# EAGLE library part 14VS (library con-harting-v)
CONNECTOR
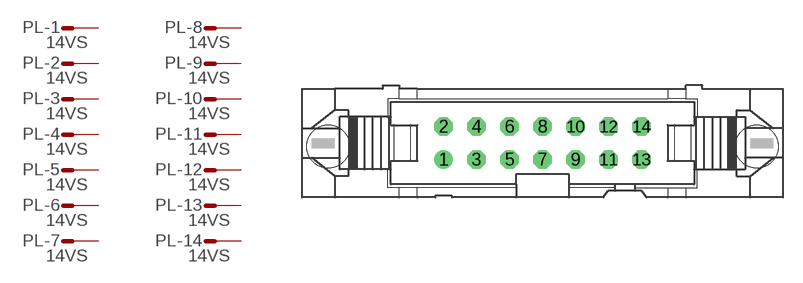
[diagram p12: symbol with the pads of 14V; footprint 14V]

Designator prefix PL; gates -1=M -2=M -3=M -4=M -5=M -6=M -7=M -8=M -9=M -10=M -11=M -12=M -13=M -14=M

## 14VS (OC_FARNELL: unknown; OC_NEWARK: unknown)  [14V]
1  -1:S  pas
2  -2:S  pas
3  -3:S  pas
4  -4:S  pas
5  -5:S  pas
6  -6:S  pas
7  -7:S  pas
8  -8:S  pas
9  -9:S  pas
10  -10:S  pas
11  -11:S  pas
12  -12:S  pas
13  -13:S  pas
14  -14:S  pas

## Footprint 14V (pad centres in mm)
CONNECTOR
drill 0.914 round: 1 -7.62,-1.27
drill 0.914 octagon: 2 -7.62,1.27; 3 -5.08,-1.27; 4 -5.08,1.27; 5 -2.54,-1.27; 6 -2.54,1.27; 7 0,-1.27; 8 0,1.27; 9 2.54,-1.27; 10 2.54,1.27; 11 5.08,-1.27; 12 5.08,1.27; 13 7.62,-1.27; 14 7.62,1.27
hole 3.302 at 16.51,-0.254
hole 3.302 at -16.51,-0.254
